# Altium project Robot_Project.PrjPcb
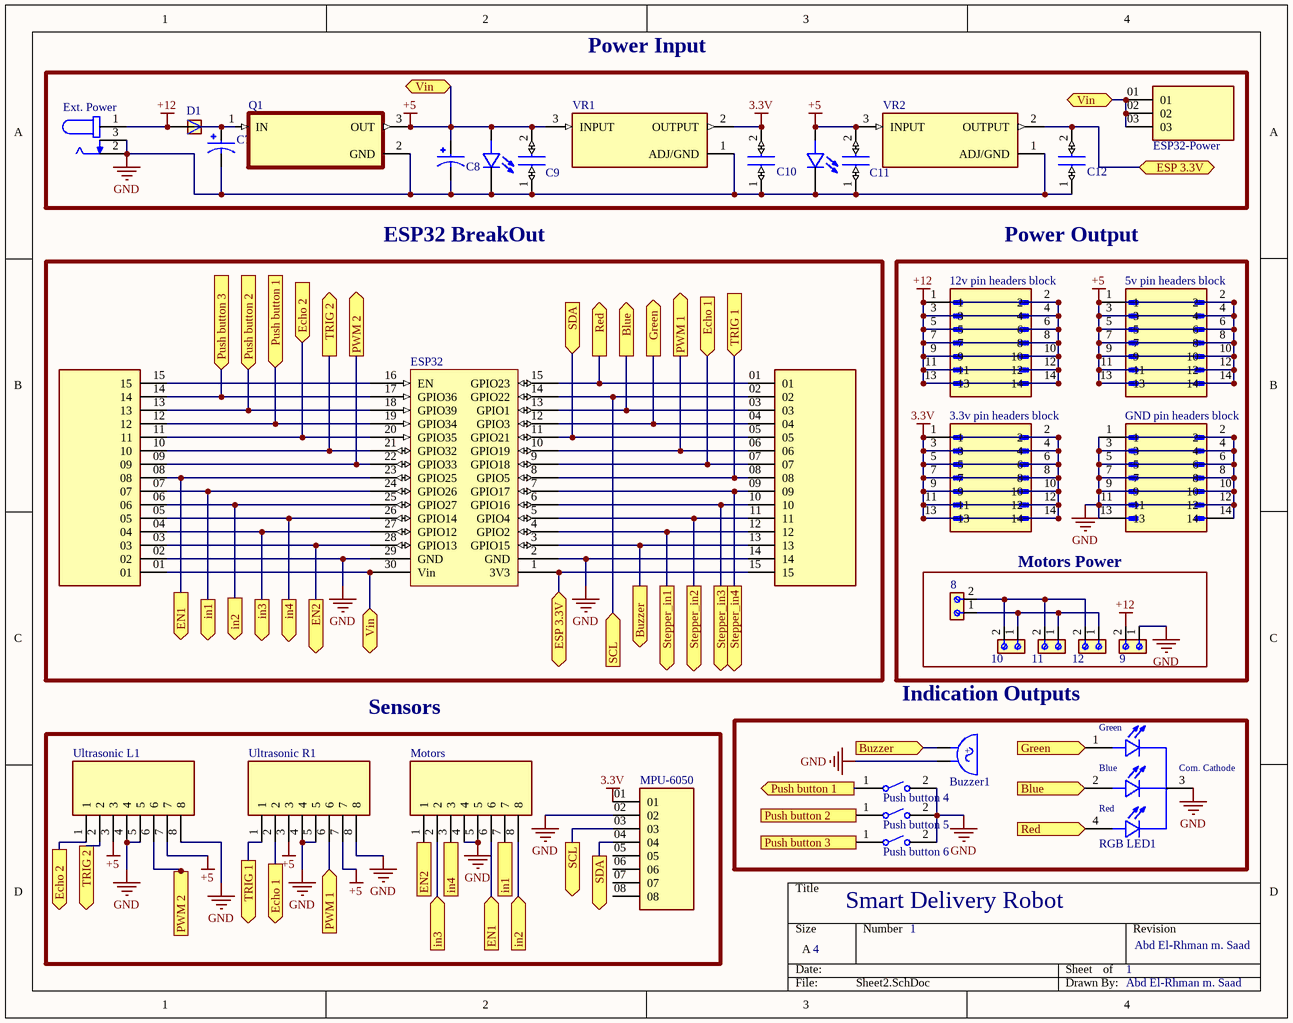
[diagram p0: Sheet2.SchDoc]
2 sheets, 75 parts. Net scope: flat (ports and power ports of the same name join across sheets).
Board file: PCB1.PcbDoc
Sheets:
  Sheet2.SchDoc
  Sheet1_draft.SchDoc

## Sheet Sheet2.SchDoc: Smart Delivery Robot
size A; Date: 27/12/2023; DrawnBy: Abd El-Rhman m. Saad; Engineer: Abd El-Rhman m. Saad; SheetNumber: 2; SheetTotal: 2

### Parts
(Parts that share a designator on the sheet are numbered #1, #2 ... from top to bottom, then left to right.)
1  LED 5mm  [LED 5mm]  (value not drawn)
2  LED 5mm  [LED 5mm]  (value not drawn)
3.3v_pin_headers_block  3.3v pin headers block  [AMPHENOL_52601-S14-4LF]  (value not drawn)
5v_pin_headers_block  5v pin headers block  [AMPHENOL_52601-S14-4LF]  (value not drawn)
8  From Buck  [691213510002]  (value not drawn)
9  From Buck  [691213510002]  (value not drawn)
10  From Buck  [691213510002]  (value not drawn)
11  From Buck  [691213510002]  (value not drawn)
12  From Buck  [691213510002]  (value not drawn)
12v_pin_headers_block  12v pin headers block  [AMPHENOL_52601-S14-4LF]  (value not drawn)
Buzzer1  Buzzer  [Buzzer 5V]  (value not drawn)
C7  CAP  33UF 50V RADIAL  [CAP  33UF 50V RADIAL]  (value not drawn)
C8  CAP  33UF 50V RADIAL  [CAP  33UF 50V RADIAL]  (value not drawn)
C9  Ceramic Capacitor 100nF  [C320C]  (value not drawn)
C10  Ceramic Capacitor 100nF  [C320C]  (value not drawn)
C11  Ceramic Capacitor 100nF  [C320C]  (value not drawn)
C12  Ceramic Capacitor 100nF  [C320C]  (value not drawn)
D1  RL207  [DIOAD1300W80L670D310]  (value not drawn)
ESP32#1  ESP32DEVKITV1  [ESP32DEVKITV1]  (value not drawn)
ESP32-Power  TS-103-T-A-1  [SAMTEC_TS-103-T-A-1]  (value not drawn)
Ext._Power#1  DC Power Jack Female Socket  [DC Power Jack Female Socket]  (value not drawn)
GND_pin_headers_block  GND pin headers block  [AMPHENOL_52601-S14-4LF]  (value not drawn)
J1  TS-115-T-A-1  [SAMTEC_TS-115-T-A-1]  (value not drawn)
J2  TS-115-T-A-1  [SAMTEC_TS-115-T-A-1]  (value not drawn)
Motors  Pin header female block 8 pin  [Pin header female block 8 pin]  (value not drawn)
MPU-6050#1  MPU-6050  [MPU-6050]  (value not drawn)
Push_button_4  FSM8JRT  [TE_FSM8JRT]  (value not drawn)
Push_button_5  FSM8JRT  [TE_FSM8JRT]  (value not drawn)
Push_button_6  FSM8JRT  [TE_FSM8JRT]  (value not drawn)
Q1  LM7805CT  [TO254P1054X470X1955-3]  (value not drawn)
RGB_LED1  common cathode  [LED RGB 5mm]  (value not drawn)
Ultrasonic_L1  Pin header female block 8 pin  [Pin header female block 8 pin]  (value not drawn)
Ultrasonic_R1  Pin header female block 8 pin  [Pin header female block 8 pin]  (value not drawn)
VR1  LM1117T-3.3  [TO254P1054X470X1955-3]  (value not drawn)
VR2  LM1117T-3.3  [TO254P1054X470X1955-3]  (value not drawn)

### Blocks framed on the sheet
Power Input: 1 2 C7-C12 D1 ESP32-Power Ext._Power#1 Q1 VR1 VR2
ESP32 BreakOut: ESP32#1 J1 J2
Power Output: 3.3v_pin_headers_block 5v_pin_headers_block 12v_pin_headers_block GND_pin_headers_block
Motors Power: 8-12
Indication Outputs: Buzzer1 Push_button_4-Push_button_6 RGB_LED1
Sensors: Motors MPU-6050#1 Ultrasonic_L1 Ultrasonic_R1

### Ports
Blue (in, see Sheet1[2B], Sheet1[4B], Sheet2[2B]), Blue (out, see Sheet1[2B], Sheet1[4B], Sheet2[4D]), Buzzer (in, see Sheet1[2C], Sheet1[4A], Sheet2[2C]), Buzzer (out, see Sheet1[2C], Sheet1[4A], Sheet2[3C]), Echo 1 (in, see Sheet1[3B], Sheet1[4B], Sheet2[1D]), Echo 1 (out, see Sheet1[3B], Sheet1[4B], Sheet2[3B]), Echo 2 (in, see Sheet1[1B], Sheet1[3B], Sheet2[1D]), Echo 2 (out, see Sheet1[1B], Sheet1[3B], Sheet2[1B]), EN1 (in, see Sheet1[1C], Sheet1[4C], Sheet2[1C]), EN1 (out, see Sheet1[1C], Sheet1[4C], Sheet2[2D]), EN2 (in, see Sheet1[2C], Sheet1[4C], Sheet2[1C]), EN2 (out, see Sheet1[2C], Sheet1[4C], Sheet2[2D]), ESP 3.3V (bidir, see Sheet1[2C], Sheet1[3A], Sheet2[2C]), ESP 3.3V (bidir, see Sheet1[2C], Sheet1[3A], Sheet2[4A]), Green (in, see Sheet1[3B], Sheet1[4B], Sheet2[3B]), Green (out, see Sheet1[3B], Sheet1[4B], Sheet2[4C]), in1 (in, see Sheet1[1C], Sheet1[4C], Sheet2[1C]), in1 (out, see Sheet1[1C], Sheet1[4C], Sheet2[2D]), in2 (in, see Sheet1[1C], Sheet1[4C], Sheet2[1C]), in2 (out, see Sheet1[1C], Sheet1[4C], Sheet2[2D]), in3 (in, see Sheet1[1C], Sheet1[4C], Sheet2[1C]), in3 (out, see Sheet1[1C], Sheet1[4C], Sheet2[2D]), in4 (in, see Sheet1[1C], Sheet1[4C], Sheet2[1C]), in4 (out, see Sheet1[1C], Sheet1[4C], Sheet2[2D]), Push button 1 (in, see Sheet1[1B], Sheet1[4C], Sheet2[3D]), Push button 1 (out, see Sheet1[1B], Sheet1[4C], Sheet2[1B]), Push button 2 (in, see Sheet1[1B], Sheet1[4D], Sheet2[3D]), Push button 2 (out, see Sheet1[1B], Sheet1[4D], Sheet2[1B]), Push button 3 (in, see Sheet1[1B], Sheet1[4D], Sheet2[3D]), Push button 3 (out, see Sheet1[1B], Sheet1[4D], Sheet2[1B]), PWM 1 (in, see Sheet1[3B], Sheet1[4B], Sheet2[3B]), PWM 1 (out, see Sheet1[3B], Sheet1[4B], Sheet2[2D]), PWM 2 (in, see Sheet1[2B], Sheet1[4B], Sheet2[2B]), PWM 2 (out, see Sheet1[2B], Sheet1[4B], Sheet2[1D]), Red (in, see Sheet1[2B], Sheet1[4B], Sheet2[2B]), Red (out, see Sheet1[2B], Sheet1[4B], Sheet2[4D]), SCL (in, see Sheet1[2C], Sheet1[3C], Sheet2[2D]), SCL (out, see Sheet1[2C], Sheet1[3C], Sheet2[2C]), SDA (in, see Sheet1[2B], Sheet1[4C], Sheet2[2D]), SDA (out, see Sheet1[2B], Sheet1[4C], Sheet2[2B]), Stepper_in1 (out, see Sheet1[2C]), Stepper_in2 (out, see Sheet1[3C]), Stepper_in3 (out, see Sheet1[3C]), Stepper_in4 (out, see Sheet1[3C]), TRIG 1 (in, see Sheet1[3B], Sheet1[4B], Sheet2[1D]), TRIG 1 (out, see Sheet1[3B], Sheet1[4B], Sheet2[3B]), TRIG 2 (out, see Sheet1[1B], Sheet1[3B], Sheet2[1D]), TRIG 2 (out, see Sheet1[1B], Sheet1[3B], Sheet2[2B]), Vin (bidir, see Sheet1[2A], Sheet1[2C], Sheet2[2A], Sheet2[2C]), Vin (bidir, see Sheet1[2A], Sheet1[2C], Sheet2[2A], Sheet2[4A]), Vin (bidir, see Sheet1[2A], Sheet1[2C], Sheet2[2C], Sheet2[4A])

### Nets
3.3V: 3.3v_pin_headers_block.1 3.3v_pin_headers_block.2 3.3v_pin_headers_block.3 3.3v_pin_headers_block.4 3.3v_pin_headers_block.5 3.3v_pin_headers_block.6 3.3v_pin_headers_block.7 3.3v_pin_headers_block.8 3.3v_pin_headers_block.9 3.3v_pin_headers_block.10 3.3v_pin_headers_block.11 3.3v_pin_headers_block.12 3.3v_pin_headers_block.13 3.3v_pin_headers_block.14 C10.2 MPU-6050#1.01 VR1.2(OUTPUT)
+5: 1.A 2.A 5v_pin_headers_block.1 5v_pin_headers_block.2 5v_pin_headers_block.3 5v_pin_headers_block.4 5v_pin_headers_block.5 5v_pin_headers_block.6 5v_pin_headers_block.7 5v_pin_headers_block.8 5v_pin_headers_block.9 5v_pin_headers_block.10 5v_pin_headers_block.11 5v_pin_headers_block.12 5v_pin_headers_block.13 5v_pin_headers_block.14 C8.P C9.2 C11.2 ESP32#1.30(Vin) ESP32-Power.01 ESP32-Power.02 ESP32-Power.03 J2.01 Q1.3(OUT) Ultrasonic_L1.3 Ultrasonic_L1.7 Ultrasonic_R1.3 Ultrasonic_R1.7 VR1.3(INPUT) VR2.3(INPUT) ; port Vin
+12: 9.2 12v_pin_headers_block.1 12v_pin_headers_block.2 12v_pin_headers_block.3 12v_pin_headers_block.4 12v_pin_headers_block.5 12v_pin_headers_block.6 12v_pin_headers_block.7 12v_pin_headers_block.8 12v_pin_headers_block.9 12v_pin_headers_block.10 12v_pin_headers_block.11 12v_pin_headers_block.12 12v_pin_headers_block.13 12v_pin_headers_block.14 D1.A Ext._Power#1.1
GND: 1.C 2.C 9.1 Buzzer1.NEG C7.N C8.N C9.1 C10.1 C11.1 C12.1 ESP32#1.2(GND) ESP32#1.29(GND) Ext._Power#1.2 Ext._Power#1.3 GND_pin_headers_block.1 GND_pin_headers_block.2 GND_pin_headers_block.3 GND_pin_headers_block.4 GND_pin_headers_block.5 GND_pin_headers_block.6 GND_pin_headers_block.7 GND_pin_headers_block.8 GND_pin_headers_block.9 GND_pin_headers_block.10 GND_pin_headers_block.11 GND_pin_headers_block.12 GND_pin_headers_block.13 GND_pin_headers_block.14 J1.14 J2.02 Motors.4 Motors.5 MPU-6050#1.02 Push_button_4.2 Push_button_5.2 Push_button_6.2 Q1.2(GND) RGB_LED1.3(Com._Cathode) Ultrasonic_L1.4 Ultrasonic_L1.5 Ultrasonic_L1.8 Ultrasonic_R1.4 Ultrasonic_R1.5 Ultrasonic_R1.8 VR1.1(ADJ/GND) VR2.1(ADJ/GND)
Net8_1: 8.1 10.1 11.1 12.1
Net8_2: 8.2 10.2 11.2 12.2
NetBuzzer_POS: Buzzer1.POS ESP32#1.3(GPIO15) J1.13 ; port Buzzer
NetC5_2: C12.2 ESP32#1.1(3V3) J1.15 VR2.2(OUTPUT) ; port ESP 3.3V
NetC7_P: C7.P D1.C Q1.1(IN)
NetESP32#1_4: ESP32#1.4(GPIO2) J1.12 ; port Stepper_in1
NetESP32#1_5: ESP32#1.5(GPIO4) J1.11 ; port Stepper_in2
NetESP32#1_6: ESP32#1.6(GPIO16) J1.10 ; port Stepper_in3
NetESP32#1_7: ESP32#1.7(GPIO17) J1.09 ; port Stepper_in4
NetESP32#1_8: ESP32#1.8(GPIO5) J1.08 Ultrasonic_R1.1 ; port TRIG 1
NetESP32#1_9: ESP32#1.9(GPIO18) J1.07 Ultrasonic_R1.2 ; port Echo 1
NetESP32#1_10: ESP32#1.10(GPIO19) J1.06 Ultrasonic_R1.6 ; port PWM 1
NetESP32#1_11: ESP32#1.11(GPIO21) J1.05 MPU-6050#1.04 ; port SDA
NetESP32#1_12: ESP32#1.12(GPIO3) J1.04 RGB_LED1.1(Green) ; port Green
NetESP32#1_13: ESP32#1.13(GPIO1) J1.03 RGB_LED1.2(BLUE) ; port Blue
NetESP32#1_14: ESP32#1.14(GPIO22) J1.02 MPU-6050#1.03 ; port SCL
NetESP32#1_15: ESP32#1.15(GPIO23) J1.01 RGB_LED1.4(Red) ; port Red
NetESP32#1_16: ESP32#1.16(EN) J2.15
NetESP32#1_17: ESP32#1.17(GPIO36) J2.14 Push_button_6.1 ; port Push button 3
NetESP32#1_18: ESP32#1.18(GPIO39) J2.13 Push_button_5.1 ; port Push button 2
NetESP32#1_19: ESP32#1.19(GPIO34) J2.12 Push_button_4.1 ; port Push button 1
NetESP32#1_20: ESP32#1.20(GPIO35) J2.11 Ultrasonic_L1.1 ; port Echo 2
NetESP32#1_21: ESP32#1.21(GPIO32) J2.10 Ultrasonic_L1.2 ; port TRIG 2
NetESP32#1_22: ESP32#1.22(GPIO33) J2.09 Ultrasonic_L1.6 ; port PWM 2
NetESP32#1_23: ESP32#1.23(GPIO25) J2.08 Motors.6 ; port EN1
NetESP32#1_24: ESP32#1.24(GPIO26) J2.07 Motors.7 ; port in1
NetESP32#1_25: ESP32#1.25(GPIO27) J2.06 Motors.8 ; port in2
NetESP32#1_26: ESP32#1.26(GPIO14) J2.05 Motors.3 ; port in4
NetESP32#1_27: ESP32#1.27(GPIO12) J2.04 Motors.2 ; port in3
NetESP32#1_28: ESP32#1.28(GPIO13) J2.03 Motors.1 ; port EN2

Not connected (* = marked no-connect by the designer): MPU-6050#1 05 06 07 08

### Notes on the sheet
- 4
- 1

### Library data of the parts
1 2 = LED 5mm: Red 623nm LED Indication - Discrete 1.9V Radial; MF: {'manufacturer': u'Wurth Elektronik'}; MP: 151054RS03000
3.3v_pin_headers_block 5v_pin_headers_block 12v_pin_headers_block GND_pin_headers_block = 52601-S14-4LF: MF: {'manufacturer': u'Amphenol ICC (FCI)'}
8-12 = Terminal Block: 2 Position Wire to Board Terminal Block Horizontal with Board 0.200 (5.08mm) Through Hole; MF: Wurth Electronics
Buzzer1 = Buzzer 5V: BUZZER 2.3KHZ 4-6VDC; MF: {'manufacturer': u'Soberton Inc.'}; MP: WST-1205S
C7 C8 = CAP  33UF 50V RADIAL: NHG-A; MF: {'manufacturer': u'Panasonic'}; MP: ECA1HHG330I
C9-C12 = Ceramic Capacitor 100nF: 0.1ÂµF Â±20% 50V Ceramic Capacitor Z5U Radial; MF: KEMET; MP: C320C104M5U5TA
D1 = RL207: Semiconductors and Actives, Power Diodes, Discretes (diodes, transistors, thyristors ...), Diodes; MF: {'manufacturer': u'Diodes Inc.'}
ESP32-Power = TS-103-T-A-1: MF: {'manufacturer': u'Samtec'}
Ext._Power#1 = DC Power Jack Female Socket: 2.0 mm Center Pin, 2.5 A, Right Angle, Through Hole, Dc Power Jack Connector; MF: {'manufacturer': u'CUI Devices'}; MP: PJ-002A
J1 J2 = TS-115-T-A-1: MF: {'manufacturer': u'Samtec'}
Motors Ultrasonic_L1 Ultrasonic_R1 = Pin header female block 8 pin: MF: {'manufacturer': u'TE Connectivity'}; MP: 5-534998-4
Push_button_4-Push_button_6 = FSM8JRT: Tactile Switches PUSHBUTTON SWITCH TACT; MF: {'manufacturer': u'TE Connectivity'}
Q1 = LM7805CT/NOPB: MF: {'manufacturer': u'Texas Instruments'}
RGB_LED1 = LED RGB 5mm: MF: {'manufacturer': u'Kingbright'}; MP: WP154A4SUREQBFZGC
VR1 VR2 = LM1117T-3.3/NOPB: MF: {'manufacturer': u'Texas Instruments'}

## Sheet Sheet1_draft.SchDoc
size A; SheetNumber: 1; SheetTotal: 1
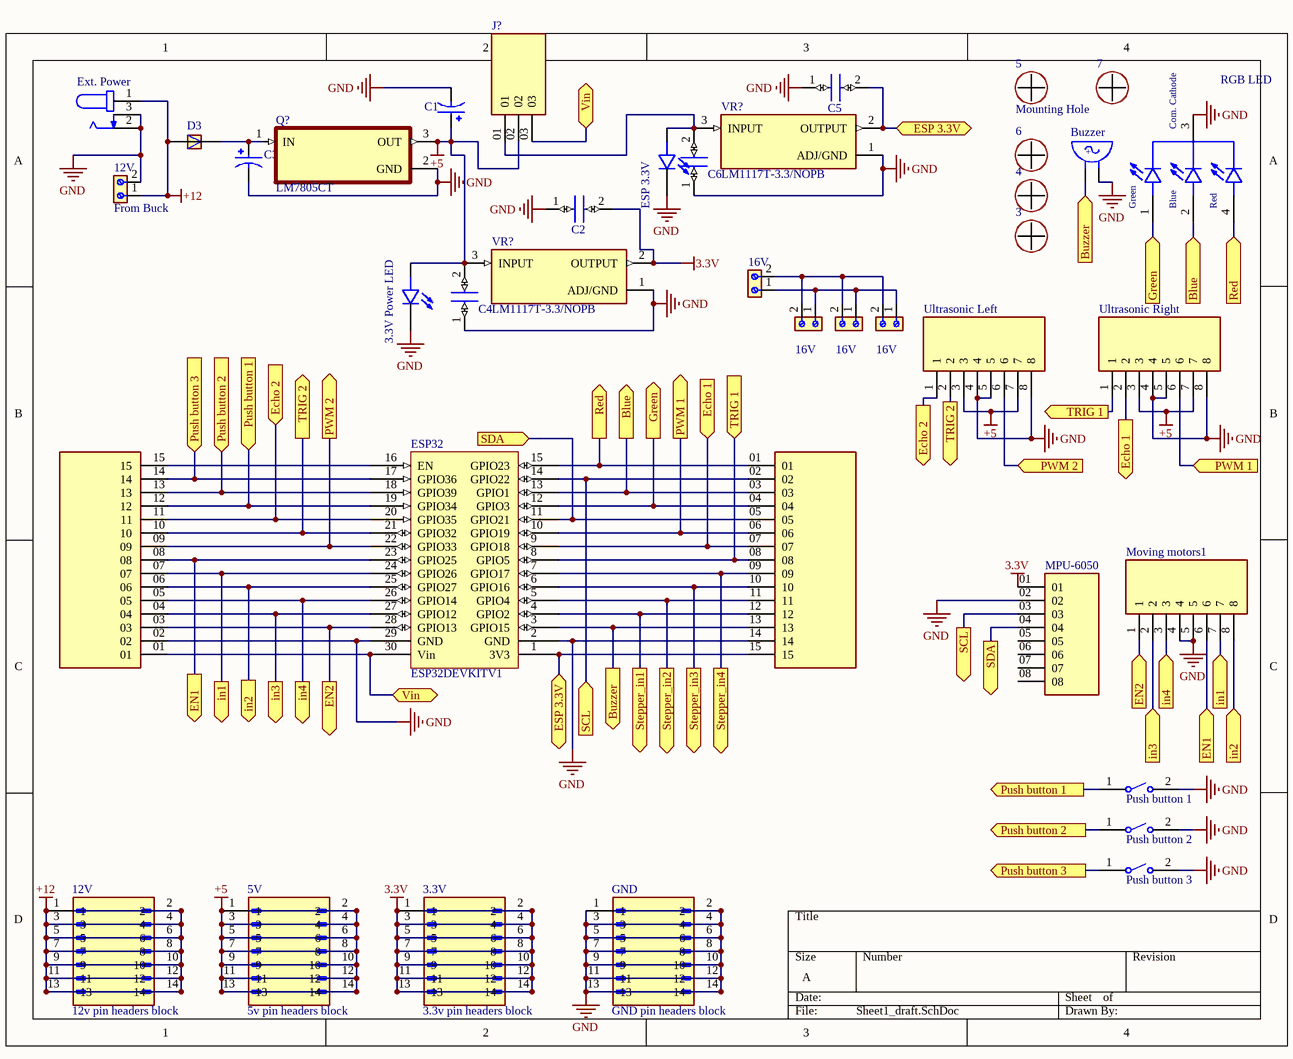
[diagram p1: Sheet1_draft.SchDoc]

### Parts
(Parts that share a designator on the sheet are numbered #1, #2 ... from top to bottom, then left to right.)
3  Mounting Hole  [PCBComponent_1]  (value not drawn)
3.3V  3.3v pin headers block  [AMPHENOL_52601-S14-4LF]
3.3V_Power_LED  LED 5mm  [LED 5mm]  (value not drawn)
4  Mounting Hole  [PCBComponent_1]  (value not drawn)
5  Mounting Hole  [PCBComponent_1]
5V  5v pin headers block  [AMPHENOL_52601-S14-4LF]
6  Mounting Hole  [PCBComponent_1]  (value not drawn)
7  Mounting Hole  [PCBComponent_1]  (value not drawn)
12V#1  From Buck  [691213510002]
12V#2  12v pin headers block  [AMPHENOL_52601-S14-4LF]
16V#1  From Buck  [691213510002]  (value not drawn)
16V#2  From Buck  [691213510002]  (value not drawn)
16V#3  From Buck  [691213510002]  (value not drawn)
16V#4  From Buck  [691213510002]  (value not drawn)
Buzzer  Buzzer  [Buzzer 5V]  (value not drawn)
C1  CAP  33UF 50V RADIAL  [CAP  33UF 50V RADIAL]  (value not drawn)
C2  Ceramic Capacitor 100nF  [C320C]  (value not drawn)
C3  CAP  33UF 50V RADIAL  [CAP  33UF 50V RADIAL]  (value not drawn)
C4  Ceramic Capacitor 100nF  [C320C]  (value not drawn)
C5  Ceramic Capacitor 100nF  [C320C]  (value not drawn)
C6  Ceramic Capacitor 100nF  [C320C]  (value not drawn)
D3  RL207  [DIOAD1300W80L670D310]  (value not drawn)
ESP32#2  ESP32DEVKITV1  [ESP32DEVKITV1]
ESP_3.3V  LED 5mm  [LED 5mm]  (value not drawn)
Ext._Power#2  DC Power Jack Female Socket  [DC Power Jack Female Socket]  (value not drawn)
GND  GND pin headers block  [AMPHENOL_52601-S14-4LF]
J5  TS-115-T-A-1  [SAMTEC_TS-115-T-A-1]  (value not drawn)
J6  TS-115-T-A-1  [SAMTEC_TS-115-T-A-1]  (value not drawn)
J?  TS-103-T-A-1  [SAMTEC_TS-103-T-A-1]  (value not drawn)
Moving_motors1  Pin header female block 8 pin  [Pin header female block 8 pin]  (value not drawn)
MPU-6050#2  MPU-6050  [MPU-6050]  (value not drawn)
Push_button_1  FSM8JRT  [TE_FSM8JRT]  (value not drawn)
Push_button_2  FSM8JRT  [TE_FSM8JRT]  (value not drawn)
Push_button_3  FSM8JRT  [TE_FSM8JRT]  (value not drawn)
Q?  LM7805CT  [TO254P1054X470X1955-3]
RGB_LED  common cathode  [LED RGB 5mm]  (value not drawn)
Ultrasonic_Left  Pin header female block 8 pin  [Pin header female block 8 pin]  (value not drawn)
Ultrasonic_Right  Pin header female block 8 pin  [Pin header female block 8 pin]  (value not drawn)
VR?#1  LM1117T-3.3/NOPB  [TO254P1054X470X1955-3]
VR?#2  LM1117T-3.3/NOPB  [TO254P1054X470X1955-3]

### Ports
Blue (in, see Sheet1[2B]), Blue (out, see Sheet1[4B]), Buzzer (in, see Sheet1[2C]), Buzzer (out, see Sheet1[4A]), Echo 1 (in, see Sheet1[4B]), Echo 1 (out, see Sheet1[3B]), Echo 2 (in, see Sheet1[3B]), Echo 2 (out, see Sheet1[1B]), EN1 (in, see Sheet1[1C]), EN1 (out, see Sheet1[4C]), EN2 (in, see Sheet1[2C]), EN2 (out, see Sheet1[4C]), ESP 3.3V (bidir, see Sheet1[2C]), ESP 3.3V (bidir, see Sheet1[3A]), Green (in, see Sheet1[3B]), Green (out, see Sheet1[4B]), in1 (in, see Sheet1[1C]), in1 (out, see Sheet1[4C]), in2 (in, see Sheet1[1C]), in2 (out, see Sheet1[4C]), in3 (in, see Sheet1[1C]), in3 (out, see Sheet1[4C]), in4 (in, see Sheet1[1C]), in4 (out, see Sheet1[4C]), Push button 1 (in, see Sheet1[4C]), Push button 1 (out, see Sheet1[1B]), Push button 2 (in, see Sheet1[4D]), Push button 2 (out, see Sheet1[1B]), Push button 3 (in, see Sheet1[4D]), Push button 3 (out, see Sheet1[1B]), PWM 1 (in, see Sheet1[3B]), PWM 1 (out, see Sheet1[4B]), PWM 2 (in, see Sheet1[2B]), PWM 2 (out, see Sheet1[4B]), Red (in, see Sheet1[2B]), Red (out, see Sheet1[4B]), SCL (in, see Sheet1[3C]), SCL (out, see Sheet1[2C]), SDA (in, see Sheet1[4C]), SDA (out, see Sheet1[2B]), Stepper_in1 (out), Stepper_in2 (out), Stepper_in3 (out), Stepper_in4 (out), TRIG 1 (in, see Sheet1[4B]), TRIG 1 (out, see Sheet1[3B]), TRIG 2 (out, see Sheet1[1B]), TRIG 2 (out, see Sheet1[3B]), Vin (bidir, see Sheet1[2A]), Vin (bidir, see Sheet1[2C])

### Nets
3.3V: 3.3V.1 3.3V.2 3.3V.3 3.3V.4 3.3V.5 3.3V.6 3.3V.7 3.3V.8 3.3V.9 3.3V.10 3.3V.11 3.3V.12 3.3V.13 3.3V.14 C2.2 MPU-6050#2.01 VR?#2.2(OUTPUT)
+5: 3.3V_Power_LED.A 5V.1 5V.2 5V.3 5V.4 5V.5 5V.6 5V.7 5V.8 5V.9 5V.10 5V.11 5V.12 5V.13 5V.14 C1.P C4.2 ESP32#2.30(Vin) J6.01 J?.02 J?.03 Q?.3(OUT) Ultrasonic_Left.3 Ultrasonic_Left.7 Ultrasonic_Right.3 Ultrasonic_Right.7 VR?#2.3(INPUT) ; port Vin
+12: 12V#1.1 12V#2.1 12V#2.2 12V#2.3 12V#2.4 12V#2.5 12V#2.6 12V#2.7 12V#2.8 12V#2.9 12V#2.10 12V#2.11 12V#2.12 12V#2.13 12V#2.14 D3.A Ext._Power#2.1
GND: 3.3V_Power_LED.C 12V#1.2 Buzzer.NEG C1.N C2.1 C3.N C4.1 C5.1 C6.1 ESP32#2.2(GND) ESP32#2.29(GND) ESP_3.3V.C Ext._Power#2.2 Ext._Power#2.3 GND.1 GND.2 GND.3 GND.4 GND.5 GND.6 GND.7 GND.8 GND.9 GND.10 GND.11 GND.12 GND.13 GND.14 J5.14 J6.02 Moving_motors1.4 Moving_motors1.5 MPU-6050#2.02 Push_button_1.2 Push_button_2.2 Push_button_3.2 Q?.2(GND) RGB_LED.3(Com._Cathode) Ultrasonic_Left.4 Ultrasonic_Left.5 Ultrasonic_Left.8 Ultrasonic_Right.4 Ultrasonic_Right.5 Ultrasonic_Right.8 VR?#1.1(ADJ/GND) VR?#2.1(ADJ/GND)
Net16V#1_1: 16V#1.1 16V#2.1 16V#3.1 16V#4.1
Net16V#1_2: 16V#1.2 16V#2.2 16V#3.2 16V#4.2
NetBuzzer_POS: Buzzer.POS ESP32#2.3(GPIO15) J5.13 ; port Buzzer
NetC3_P: C3.P D3.C Q?.1(IN)
NetC5_2: C5.2 ESP32#2.1(3V3) J5.15 VR?#1.2(OUTPUT) ; port ESP 3.3V
NetC6_2: C6.2 ESP_3.3V.A J?.01 VR?#1.3(INPUT)
NetESP32#1_4: ESP32#2.4(GPIO2) J5.12 ; port Stepper_in1
NetESP32#1_5: ESP32#2.5(GPIO4) J5.11 ; port Stepper_in2
NetESP32#1_6: ESP32#2.6(GPIO16) J5.10 ; port Stepper_in3
NetESP32#1_7: ESP32#2.7(GPIO17) J5.09 ; port Stepper_in4
NetESP32#1_8: ESP32#2.8(GPIO5) J5.08 Ultrasonic_Right.1 ; port TRIG 1
NetESP32#1_9: ESP32#2.9(GPIO18) J5.07 Ultrasonic_Right.2 ; port Echo 1
NetESP32#1_10: ESP32#2.10(GPIO19) J5.06 Ultrasonic_Right.6 ; port PWM 1
NetESP32#1_11: ESP32#2.11(GPIO21) J5.05 MPU-6050#2.04 ; port SDA
NetESP32#1_12: ESP32#2.12(GPIO3) J5.04 RGB_LED.1(Green) ; port Green
NetESP32#1_13: ESP32#2.13(GPIO1) J5.03 RGB_LED.2(BLUE) ; port Blue
NetESP32#1_14: ESP32#2.14(GPIO22) J5.02 MPU-6050#2.03 ; port SCL
NetESP32#1_15: ESP32#2.15(GPIO23) J5.01 RGB_LED.4(Red) ; port Red
NetESP32#1_17: ESP32#2.17(GPIO36) J6.14 Push_button_3.1 ; port Push button 3
NetESP32#1_18: ESP32#2.18(GPIO39) J6.13 Push_button_2.1 ; port Push button 2
NetESP32#1_19: ESP32#2.19(GPIO34) J6.12 Push_button_1.1 ; port Push button 1
NetESP32#1_20: ESP32#2.20(GPIO35) J6.11 Ultrasonic_Left.1 ; port Echo 2
NetESP32#1_21: ESP32#2.21(GPIO32) J6.10 Ultrasonic_Left.2 ; port TRIG 2
NetESP32#1_22: ESP32#2.22(GPIO33) J6.09 Ultrasonic_Left.6 ; port PWM 2
NetESP32#1_23: ESP32#2.23(GPIO25) J6.08 Moving_motors1.6 ; port EN1
NetESP32#1_24: ESP32#2.24(GPIO26) J6.07 Moving_motors1.7 ; port in1
NetESP32#1_25: ESP32#2.25(GPIO27) J6.06 Moving_motors1.8 ; port in2
NetESP32#1_26: ESP32#2.26(GPIO14) J6.05 Moving_motors1.3 ; port in4
NetESP32#1_27: ESP32#2.27(GPIO12) J6.04 Moving_motors1.2 ; port in3
NetESP32#1_28: ESP32#2.28(GPIO13) J6.03 Moving_motors1.1 ; port EN2
NetESP32#2_16: ESP32#2.16(EN) J6.15

Not connected (* = marked no-connect by the designer): MPU-6050#2 05 06 07 08

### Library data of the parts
3.3V 5V 12V#2 GND = 52601-S14-4LF: as 3.3v_pin_headers_block on sheet Sheet2
3.3V_Power_LED ESP_3.3V = LED 5mm: as 1 on sheet Sheet2
12V#1 16V#1-16V#4 = Terminal Block: as 8 on sheet Sheet2
Buzzer = Buzzer 5V: as Buzzer1 on sheet Sheet2
C1 C3 = CAP  33UF 50V RADIAL: as C7 on sheet Sheet2
C2 C4-C6 = Ceramic Capacitor 100nF: as C9 on sheet Sheet2
D3 = RL207: as D1 on sheet Sheet2
Ext._Power#2 = DC Power Jack Female Socket: as Ext._Power#1 on sheet Sheet2
J5 J6 = TS-115-T-A-1: MF: {'manufacturer': u'Samtec'}
J? = TS-103-T-A-1: MF: {'manufacturer': u'Samtec'}
Moving_motors1 Ultrasonic_Left Ultrasonic_Right = Pin header female block 8 pin: as Motors on sheet Sheet2
Push_button_1-Push_button_3 = FSM8JRT: as Push_button_4 on sheet Sheet2
Q? = LM7805CT/NOPB: as Q1 on sheet Sheet2
RGB_LED = LED RGB 5mm: as RGB_LED1 on sheet Sheet2
VR?#1 VR?#2 = LM1117T-3.3/NOPB: as VR1 on sheet Sheet2

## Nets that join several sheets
3.3V: Sheet2 (17 pins), Sheet1_draft (17 pins)
+5: Sheet2 (31 pins), Sheet1_draft (27 pins)
+12: Sheet2 (17 pins), Sheet1_draft (17 pins)
GND: Sheet2 (46 pins), Sheet1_draft (46 pins)
NetBuzzer_POS: Sheet2 (Buzzer1.POS ESP32#1.3 J1.13), Sheet1_draft (Buzzer.POS ESP32#2.3 J5.13)
NetC5_2: Sheet2 (C12.2 ESP32#1.1 J1.15 VR2.2), Sheet1_draft (C5.2 ESP32#2.1 J5.15 VR?#1.2)
NetESP32#1_4: Sheet2 (ESP32#1.4 J1.12), Sheet1_draft (ESP32#2.4 J5.12)
NetESP32#1_5: Sheet2 (ESP32#1.5 J1.11), Sheet1_draft (ESP32#2.5 J5.11)
NetESP32#1_6: Sheet2 (ESP32#1.6 J1.10), Sheet1_draft (ESP32#2.6 J5.10)
NetESP32#1_7: Sheet2 (ESP32#1.7 J1.09), Sheet1_draft (ESP32#2.7 J5.09)
NetESP32#1_8: Sheet2 (ESP32#1.8 J1.08 Ultrasonic_R1.1), Sheet1_draft (ESP32#2.8 J5.08 Ultrasonic_Right.1)
NetESP32#1_9: Sheet2 (ESP32#1.9 J1.07 Ultrasonic_R1.2), Sheet1_draft (ESP32#2.9 J5.07 Ultrasonic_Right.2)
NetESP32#1_10: Sheet2 (ESP32#1.10 J1.06 Ultrasonic_R1.6), Sheet1_draft (ESP32#2.10 J5.06 Ultrasonic_Right.6)
NetESP32#1_11: Sheet2 (ESP32#1.11 J1.05 MPU-6050#1.04), Sheet1_draft (ESP32#2.11 J5.05 MPU-6050#2.04)
NetESP32#1_12: Sheet2 (ESP32#1.12 J1.04 RGB_LED1.1), Sheet1_draft (ESP32#2.12 J5.04 RGB_LED.1)
NetESP32#1_13: Sheet2 (ESP32#1.13 J1.03 RGB_LED1.2), Sheet1_draft (ESP32#2.13 J5.03 RGB_LED.2)
NetESP32#1_14: Sheet2 (ESP32#1.14 J1.02 MPU-6050#1.03), Sheet1_draft (ESP32#2.14 J5.02 MPU-6050#2.03)
NetESP32#1_15: Sheet2 (ESP32#1.15 J1.01 RGB_LED1.4), Sheet1_draft (ESP32#2.15 J5.01 RGB_LED.4)
NetESP32#1_17: Sheet2 (ESP32#1.17 J2.14 Push_button_6.1), Sheet1_draft (ESP32#2.17 J6.14 Push_button_3.1)
NetESP32#1_18: Sheet2 (ESP32#1.18 J2.13 Push_button_5.1), Sheet1_draft (ESP32#2.18 J6.13 Push_button_2.1)
NetESP32#1_19: Sheet2 (ESP32#1.19 J2.12 Push_button_4.1), Sheet1_draft (ESP32#2.19 J6.12 Push_button_1.1)
NetESP32#1_20: Sheet2 (ESP32#1.20 J2.11 Ultrasonic_L1.1), Sheet1_draft (ESP32#2.20 J6.11 Ultrasonic_Left.1)
NetESP32#1_21: Sheet2 (ESP32#1.21 J2.10 Ultrasonic_L1.2), Sheet1_draft (ESP32#2.21 J6.10 Ultrasonic_Left.2)
NetESP32#1_22: Sheet2 (ESP32#1.22 J2.09 Ultrasonic_L1.6), Sheet1_draft (ESP32#2.22 J6.09 Ultrasonic_Left.6)
NetESP32#1_23: Sheet2 (ESP32#1.23 J2.08 Motors.6), Sheet1_draft (ESP32#2.23 J6.08 Moving_motors1.6)
NetESP32#1_24: Sheet2 (ESP32#1.24 J2.07 Motors.7), Sheet1_draft (ESP32#2.24 J6.07 Moving_motors1.7)
NetESP32#1_25: Sheet2 (ESP32#1.25 J2.06 Motors.8), Sheet1_draft (ESP32#2.25 J6.06 Moving_motors1.8)
NetESP32#1_26: Sheet2 (ESP32#1.26 J2.05 Motors.3), Sheet1_draft (ESP32#2.26 J6.05 Moving_motors1.3)
NetESP32#1_27: Sheet2 (ESP32#1.27 J2.04 Motors.2), Sheet1_draft (ESP32#2.27 J6.04 Moving_motors1.2)
NetESP32#1_28: Sheet2 (ESP32#1.28 J2.03 Motors.1), Sheet1_draft (ESP32#2.28 J6.03 Moving_motors1.1)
